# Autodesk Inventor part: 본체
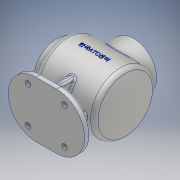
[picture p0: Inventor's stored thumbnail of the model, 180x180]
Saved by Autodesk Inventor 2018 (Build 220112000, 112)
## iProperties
Created: 2023-01
Part Number: 본체
Material: 알루미늄 6061
Document SubType Name: Modeling
Designer: home
Density: 2.7 g/cm^3
Appearance: 알루미늄 - 평지
Author: home
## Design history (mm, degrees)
sketch "스케치1"
  geometry: L1 (17, 0)-(-17, 0); L2 (17, -46)-(-17, -46); L3 (17, 46)-(-17, 46); A1 r 46 centre (-17, 0) between (-17, 46) and (-17, -46); A2 r 46 centre (17, 0) between (17, -46) and (17, 46); 1 further point
  constraints: 6 end point, 4 point on circle, 3 horizontal, 2 centre point, 2 coincident, 2 tangent, 1 midpoint
  dimensions: "d0" = 34 distance of L1.start L1.end; "d1" = 17 distance of point (0, 0) L1.start (= 0.5 x d0); "d3" = 92 diameter of A1; "d4" = 46 radius of A2
extrude "돌출1" new body sketch "스케치1" distance "d5" = 10; taper "d6" = 0 deg
sketch "스케치2"
  geometry: L1 (-30, 30)-(30, 30); L2 (30, 30)-(30, -30); L3 (30, -30)-(-30, -30); L4 (-30, -30)-(-30, 30); L5 (-30, 30)-(30, -30); L6 (30, 30)-(-30, -30); 5 further points
  constraints: 12 end point, 4 coincident, 2 midpoint, 2 parallel, 1 horizontal, 1 perpendicular
  dimensions: "d7" = 60 distance of L2.end L3.end; "d8" = 60 distance of L1.end L2.end
hole "구멍1" sketch "스케치2" at (-30, 30), (-30, -30), (30, -30), (30, 30) diameter "d9" = 9; stored, may be unused: countersink angle "d13" = 90 deg, drill point angle "d15" = 118 deg; dims "d10" = 6, "d11" = 4, "d12" = 2, "d14" = 8
sketch "스케치3"
  geometry: L1 (-85.249, 80)-(98.9, 80); L2 (17, 0)-(-17, 0) reference; L3 (-51, 80)-(-51, 130); L4 (-51, 130)-(48.087, 130); L5 (59, 130)-(59, 80); L6 (-63, 0)-(-17, 0) reference; L7 (-63, 0)-(-63, 145.307); L8 (-46, 80)-(-46, 125); L9 (-46, 125)-(44.83, 125); L10 (54, 125)-(54, 80); L11 (-51, 118)-(-63, 118); L12 (-63, 118)-(-63, 107); L13 (-63, 107)-(-46, 107); L14 (-51, 130)-(-51, 118); L15 (-46, 107)-(-46, 125); L16 (54, 80)-(59, 80); A1 r 120 centre (-61, 80) between (59, 80) and (48.087, 130); A2 r 115 centre (-61, 80) between (54, 80) and (44.83, 125); 1 further point
  constraints: 28 end point, 10 point on line, 7 perpendicular, 4 point on circle, 2 centre point, 2 collinear, 2 tangent, 2 vertical, 1 horizontal, 1 parallel
  dimensions: "d16" = 80 distance between parallel lines of L2 L1; "d17" = 100 diameter of L4 L1; "d18" = 12 distance between parallel lines of L3 L7; "d19" = 110 distance between parallel lines of L5 L3; "d20" = 240 diameter of A1; "d21" = 5 distance between parallel lines of L5 L10; "d22" = 5 distance between parallel lines of L4 L9; "d23" = 5 distance between parallel lines of L3 L8; "d24" = 230 diameter of A2; "d25" = 76 diameter of L11 L1; "d26" = 54 diameter of L13 L1; "d27" = 17 distance between parallel lines of L15 L12 (derived)
revolve "회전1" sketch "스케치3" stored, may be unused: angle "d28" = 90 deg
sketch "스케치4"
  geometry: L1 (-17, 10)-(-63, 10) reference; L2 (-51, 30)-(48.087, 30) reference; L3 (-34.5, 0)-(-34.5, 10) reference; L4 (44.83, 35)-(-46, 35) reference; L5 (-40, 10)-(40, 10); L6 (-40, 10)-(-33.971, 32.5); L7 (40, 10)-(33.971, 32.5); L8 (63, 10)-(17, 10) reference; L9 (-33.971, 32.5)-(33.971, 32.5); L10 (-63, 0)-(-63, 10) reference; 1 further point
  constraints: 8 end point, 2 horizontal, 1 midpoint
  dimensions: "d34" = 80 distance of L5.start L5.end; "d35" = 40 horizontal distance of point (0, 0) L5.start (= 0.5 x d34); "d36" = 105 deg angle of L1 L6; "d37" = 105 deg angle of L8 L7; "d38" = 2.5 distance between parallel lines of L2 L9
extrude "돌출2" join sketch "스케치4" stored distance "d39" = 10; taper "d40" = 0 deg
sketch "스케치5"
  geometry: L1 (10, -46)-(10, 46) reference; L2 (10, -35)-(44.293, -35); L3 (44.293, 35)-(10, 35); L4 (10, 35)-(10, -35); A1 r 50 centre (80, 0) between (44.293, -35) and (44.293, 35) reference; 1 further point
  constraints: 6 end point, 2 point on circle, 1 collinear, 1 horizontal, 1 parallel, 1 point on line
  dimensions: "d41" = 70 distance between parallel lines of L3 L2; "d42" = 35 distance from line of point (0, 0) L2 (= 0.5 x d41)
extrude "돌출3" join sketch "스케치5" stored distance "d43" = 10; taper "d44" = 0 deg
node "작업 평면1"
sketch "스케치6"
  geometry: C1 r 38 at (0, 0); 1 further point
  constraints: 1 centre point, 1 coincident
  dimensions: "d46" = 76 diameter of C1
extrude "돌출4" join sketch "스케치6" stored distance "d47" = 10; taper "d48" = 0 deg
sketch "스케치7"
  geometry: L1 (0, 32.5)-(0, -32.5); L2 (-32.5, 0)-(32.5, 0); C1 r 38 at (0, 0) reference; A1 r 32.5 centre (0, 0) between (0, 32.5) and (0, -32.5); 7 further points
  constraints: 5 coincident, 4 end point, 4 midpoint, 4 point on circle, 1 centre point, 1 perpendicular, 1 vertical
  dimensions: "d49" = 65 diameter of A1
hole "구멍2" sketch "스케치7" at (0, 32.5), (-32.5, 0), (0, -32.5), (32.5, 0) diameter "d50" = 3.242; stored, may be unused: countersink angle "d54" = 90 deg, drill point angle "d56" = 118 deg; dims "d51" = 8, "d52" = 4, "d53" = 2, "d55" = 10
sketch "스케치8"
  geometry: 2 further points
  constraints: 1 coincident
hole "구멍3" sketch "스케치8" at (0, 0) diameter "d57" = 54; stored, may be unused: countersink angle "d61" = 90 deg, drill point angle "d63" = 118 deg; dims "d58" = 8, "d59" = 4, "d60" = 2, "d62" = 10
sketch "스케치9"
  geometry: L1 (0, 32.5)-(0, -32.5); L2 (-32.5, 0)-(32.5, 0); A1 r 32.5 centre (0, 0) between (0, 32.5) and (0, -32.5); 10 further points; 1 other entity
  constraints: 5 coincident, 4 end point, 4 point on circle, 3 midpoint, 1 centre point, 1 horizontal, 1 vertical, 1 other
  dimensions: "d64" = 65 diameter of A1
hole "구멍4" sketch "스케치9" at (-32.5, 0), (0, 32.5), (0, -32.5), (32.5, 0) diameter "d65" = 3.242; stored, may be unused: countersink angle "d69" = 90 deg, drill point angle "d71" = 118 deg; dims "d66" = 8, "d67" = 4, "d68" = 2, "d70" = 10
node "작업 평면2"
sketch "스케치10"
  geometry: L1 (17, 0)-(63, 0) reference; L2 (0, 0)-(0, 177.758); L3 (-63, 42)-(-63, 118) reference; L4 (-63, 80)-(59, 80); A1 r 120 centre (-61, 80) between (48.087, 30) and (48.087, 130) reference
  constraints: 4 end point, 2 horizontal, 1 midpoint, 1 point on circle, 1 vertical
  dimensions: "d74" = 63 distance between parallel lines of L3 L2 (derived); "d75" = 80 distance between parallel lines of L1 L4
feature "엠보싱1" sketch "스케치10" dims "d0" = 34, "d1" = 17 (= 0.5 x d0), "d3" = 92, "d4" = 46, "d76" = 0.5, "d77" = 0
chamfer "모따기1" distance "d78" = 1; stored, may be unused: second distance "d79" = 2, angle "d80" = 45 deg
fillet "모깎기1" dims "d81" = 3, "d82" = 8
node "솔리드1"
other parameters: "d2" = 92, "d45" = -144
